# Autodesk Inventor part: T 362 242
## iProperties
Created: 2006-01
Part Number: T 362 242
Material: Durethan BKV30H
Document SubType Name: Modeling
Designer: I.Baliuc
Manufacturer: Standard
Standards Organization: Custom
Description: Sockel
Density: 0.94 g/cm^3
Title: Sockel
Company: Mayer & Müller AG Schaltgeräte
Zweck: für K-Auslöser
Author: T.Messerschmitt
Keywords: 213549
Revision Number: 362242
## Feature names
1. Extrusion2
2. Extrusion3
3. Rundung_0.5 [Fillet]
4. Extrusion4
5. Fase1 [Chamfer]
6. Fase2 [Chamfer]
7. Bohrung1 [Hole]
8. Extrusion5
9. Bohrung2 [Hole]
